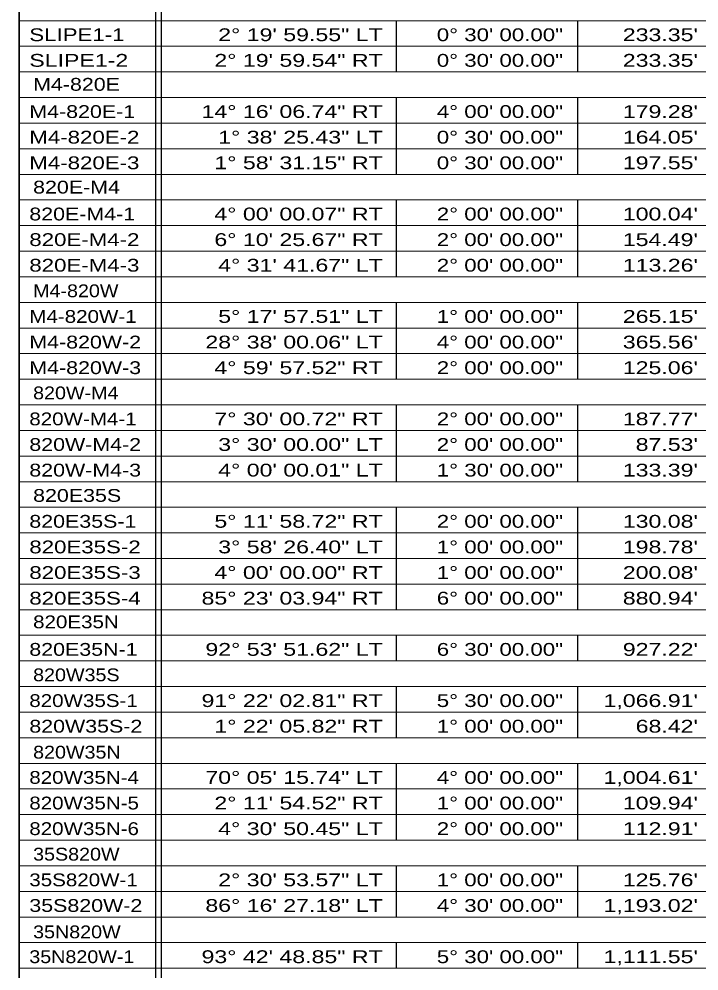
# Model space of a CAD drawing. Extents: x 1953053 to 1967065, y 7363860 to 7371201.
# Drawn here: x 1955933 to 1956571, y 7368493 to 7369385 of the extents above; entities that cross this region are included whole.
import ezdxf
from ezdxf.enums import TextEntityAlignment as Align

# ---------------------------------------------------------------- set-up
doc = ezdxf.new("R2010")
doc.units = 0
doc.header["$LTSCALE"] = 4.8
doc.layers.add('10', color=7, linetype='Continuous')
doc.layers.add('12', color=7, linetype='Continuous', lineweight=25)

msp = doc.modelspace()

# ---------------------------------------------------------------- linework, layer by layer
at = {"layer": '12', "lineweight": 35}
msp.add_line((1955933.385, 7370164.879), (1955933.385, 7367607.746), dxfattribs=at)
at = {"layer": '12'}
for p, q in [((1956061.23, 7370136.079), (1956061.23, 7367607.746)), ((1956066.717, 7370136.079), (1956066.717, 7367607.746)), ((1956286.717, 7369383.746), (1956286.717, 7369335.746)), ((1956456.717, 7369383.746), (1956456.717, 7369335.746)), ((1956286.717, 7369311.746), (1956286.717, 7369239.746)), ((1956456.717, 7369311.746), (1956456.717, 7369239.746)), ((1956286.717, 7369215.746), (1956286.717, 7369143.746)), ((1956456.717, 7369215.746), (1956456.717, 7369143.746)), ((1956286.717, 7369119.746), (1956286.717, 7369047.746)), ((1956456.717, 7369119.746), (1956456.717, 7369047.746)), ((1956286.717, 7369023.746), (1956286.717, 7368951.746)), ((1956456.717, 7369023.746), (1956456.717, 7368951.746)), ((1956286.717, 7368927.746), (1956286.717, 7368831.746)), ((1956456.717, 7368927.746), (1956456.717, 7368831.746)), ((1956286.717, 7368807.746), (1956286.717, 7368783.746)), ((1956456.717, 7368807.746), (1956456.717, 7368783.746)), ((1956286.717, 7368759.746), (1956286.717, 7368711.746)), ((1956456.717, 7368759.746), (1956456.717, 7368711.746)), ((1956286.717, 7368687.746), (1956286.717, 7368615.746)), ((1956456.717, 7368687.746), (1956456.717, 7368615.746)), ((1956286.717, 7368591.746), (1956286.717, 7368543.746)), ((1956456.717, 7368591.746), (1956456.717, 7368543.746)), ((1956286.717, 7368519.746), (1956286.717, 7368495.746)), ((1956456.717, 7368519.746), (1956456.717, 7368495.746))]:
    msp.add_line(p, q, dxfattribs=at)
at = {"layer": '12', "lineweight": 13}
for p, q in [((1955933.385, 7369383.746), (1957656.717, 7369383.746)), ((1955933.385, 7369359.746), (1957656.717, 7369359.746)), ((1955933.385, 7369335.746), (1957656.717, 7369335.746)), ((1955933.385, 7369311.746), (1957656.717, 7369311.746)), ((1955933.385, 7369287.746), (1957656.717, 7369287.746)), ((1955933.385, 7369263.747), (1957656.717, 7369263.747)), ((1955933.385, 7369239.746), (1957656.717, 7369239.746)), ((1955933.385, 7369215.746), (1957656.717, 7369215.746)), ((1955933.385, 7369191.746), (1957656.717, 7369191.746)), ((1955933.385, 7369167.746), (1957656.717, 7369167.746)), ((1955933.385, 7369143.746), (1957656.717, 7369143.746)), ((1955933.385, 7369119.746), (1957656.717, 7369119.746)), ((1955933.385, 7369095.746), (1957656.717, 7369095.746)), ((1955933.385, 7369071.746), (1957656.717, 7369071.746)), ((1955933.385, 7369047.746), (1957656.717, 7369047.746)), ((1955933.385, 7369023.746), (1957656.717, 7369023.746)), ((1955933.385, 7368999.746), (1957656.717, 7368999.746)), ((1955933.385, 7368975.746), (1957656.717, 7368975.746)), ((1955933.385, 7368951.746), (1957656.717, 7368951.746)), ((1955933.385, 7368927.746), (1957656.717, 7368927.746)), ((1955933.385, 7368903.746), (1957656.717, 7368903.746)), ((1955933.385, 7368879.746), (1957656.717, 7368879.746)), ((1955933.385, 7368855.746), (1957656.717, 7368855.746)), ((1955933.385, 7368831.746), (1957656.717, 7368831.746)), ((1955933.385, 7368807.746), (1957656.717, 7368807.746)), ((1955933.385, 7368783.746), (1957656.717, 7368783.746)), ((1955933.385, 7368759.746), (1957656.717, 7368759.746)), ((1955933.385, 7368735.746), (1957656.717, 7368735.746)), ((1955933.385, 7368711.746), (1957656.717, 7368711.746)), ((1955933.385, 7368687.746), (1957656.717, 7368687.746)), ((1955933.385, 7368663.746), (1957656.717, 7368663.746)), ((1955933.385, 7368639.746), (1957656.717, 7368639.746)), ((1955933.385, 7368615.746), (1957656.717, 7368615.746)), ((1955933.385, 7368591.746), (1957656.717, 7368591.746)), ((1955933.385, 7368567.746), (1957656.717, 7368567.746)), ((1955933.385, 7368543.746), (1957656.717, 7368543.746)), ((1955933.385, 7368519.746), (1957656.717, 7368519.746)), ((1955933.385, 7368495.746), (1957656.717, 7368495.746))]:
    msp.add_line(p, q, dxfattribs=at)

# ---------------------------------------------------------------- texts
at = {"layer": '10'}
for s, width, p in [('SLIPE1-1', 1.3, (1955943.006, 7369364.573)), ('SLIPE1-2', 1.35, (1955943.006, 7369340.573)), ('M4-820E', 1.25, (1955946.57, 7369318.084)), ('M4-820E-1', 1.25, (1955943.011, 7369292.569)), ('M4-820E-2', 1.3, (1955943.011, 7369268.569)), ('M4-820E-3', 1.3, (1955943.011, 7369244.569)), ('820E-M4', 1.25, (1955946.57, 7369221.774)), ('820E-M4-1', 1.25, (1955943.011, 7369196.569)), ('820E-M4-2', 1.3, (1955943.011, 7369172.569)), ('820E-M4-3', 1.3, (1955943.011, 7369148.569)), ('M4-820W', 1.15, (1955946.57, 7369124.623)), ('M4-820W-1', 1.2, (1955943.011, 7369100.569)), ('M4-820W-2', 1.25, (1955943.011, 7369076.569)), ('M4-820W-3', 1.25, (1955943.011, 7369052.569)), ('820W-M4', 1.15, (1955946.57, 7369028.925)), ('820W-M4-1', 1.2, (1955943.011, 7369004.569)), ('820W-M4-2', 1.25, (1955943.011, 7368980.569)), ('820W-M4-3', 1.25, (1955943.011, 7368956.569)), ('820E35S', 1.25, (1955946.57, 7368932.849)), ('820E35S-1', 1.25, (1955943.011, 7368908.569)), ('820E35S-2', 1.3, (1955943.011, 7368884.569)), ('820E35S-3', 1.3, (1955943.011, 7368860.569)), ('820E35S-4', 1.3, (1955943.011, 7368836.569)), ('820E35N', 1.2, (1955946.57, 7368814.363)), ('820E35N-1', 1.25, (1955943.011, 7368788.569)), ('820W35S', 1.15, (1955946.57, 7368764.697)), ('820W35S-1', 1.2, (1955943.011, 7368740.569)), ('820W35S-2', 1.25, (1955943.011, 7368716.569)), ('820W35N', 1.15, (1955946.57, 7368692.242)), ('820W35N-4', 1.2, (1955943.011, 7368668.569)), ('820W35N-5', 1.2, (1955943.011, 7368644.569)), ('820W35N-6', 1.2, (1955943.011, 7368620.569)), ('35S820W', 1.15, (1955946.57, 7368596.635)), ('35S820W-1', 1.2, (1955943.011, 7368572.569)), ('35S820W-2', 1.25, (1955943.011, 7368548.569)), ('35N820W', 1.15, (1955946.57, 7368523.834)), ('35N820W-1', 1.15, (1955943.011, 7368500.569))]:
    msp.add_text(s, height=12, dxfattribs=dict(at, width=width)).set_placement(p)
for s, width, p in [('2° 19\' 59.55" LT', 1.35, (1956274.239, 7369364.573)), ('0° 30\' 00.00"', 1.3, (1956443.234, 7369364.573)), ("233.35'", 1.35, (1956569.644, 7369364.573)), ('2° 19\' 59.54" RT', 1.35, (1956274.239, 7369340.573)), ('0° 30\' 00.00"', 1.3, (1956443.234, 7369340.573)), ("233.35'", 1.35, (1956569.644, 7369340.573)), ('14° 16\' 06.74" RT', 1.35, (1956274.244, 7369292.569)), ('4° 00\' 00.00"', 1.3, (1956443.239, 7369292.569)), ("179.28'", 1.35, (1956569.649, 7369292.569)), ('1° 38\' 25.43" LT', 1.35, (1956274.244, 7369268.569)), ('0° 30\' 00.00"', 1.3, (1956443.239, 7369268.569)), ("164.05'", 1.35, (1956569.649, 7369268.569)), ('1° 58\' 31.15" RT', 1.35, (1956274.244, 7369244.569)), ('0° 30\' 00.00"', 1.3, (1956443.239, 7369244.569)), ("197.55'", 1.35, (1956569.649, 7369244.569)), ('4° 00\' 00.07" RT', 1.35, (1956274.244, 7369196.569)), ('2° 00\' 00.00"', 1.3, (1956443.239, 7369196.569)), ("100.04'", 1.35, (1956569.649, 7369196.569)), ('6° 10\' 25.67" RT', 1.35, (1956274.244, 7369172.569)), ('2° 00\' 00.00"', 1.3, (1956443.239, 7369172.569)), ("154.49'", 1.35, (1956569.649, 7369172.569)), ('4° 31\' 41.67" LT', 1.35, (1956274.244, 7369148.569)), ('2° 00\' 00.00"', 1.3, (1956443.239, 7369148.569)), ("113.26'", 1.35, (1956569.649, 7369148.569)), ('5° 17\' 57.51" LT', 1.35, (1956274.244, 7369100.569)), ('1° 00\' 00.00"', 1.3, (1956443.239, 7369100.569)), ("265.15'", 1.35, (1956569.649, 7369100.569)), ('28° 38\' 00.06" LT', 1.35, (1956274.244, 7369076.569)), ('4° 00\' 00.00"', 1.3, (1956443.239, 7369076.569)), ("365.56'", 1.35, (1956569.649, 7369076.569)), ('4° 59\' 57.52" RT', 1.35, (1956274.244, 7369052.569)), ('2° 00\' 00.00"', 1.3, (1956443.239, 7369052.569)), ("125.06'", 1.35, (1956569.649, 7369052.569)), ('7° 30\' 00.72" RT', 1.35, (1956274.244, 7369004.569)), ('2° 00\' 00.00"', 1.3, (1956443.239, 7369004.569)), ("187.77'", 1.35, (1956569.649, 7369004.569)), ('3° 30\' 00.00" LT', 1.35, (1956274.244, 7368980.569)), ('2° 00\' 00.00"', 1.3, (1956443.239, 7368980.569)), ("87.53'", 1.35, (1956569.649, 7368980.569)), ('4° 00\' 00.01" LT', 1.35, (1956274.244, 7368956.569)), ('1° 30\' 00.00"', 1.3, (1956443.239, 7368956.569)), ("133.39'", 1.35, (1956569.649, 7368956.569)), ('5° 11\' 58.72" RT', 1.35, (1956274.244, 7368908.569)), ('2° 00\' 00.00"', 1.3, (1956443.239, 7368908.569)), ("130.08'", 1.35, (1956569.649, 7368908.569)), ('3° 58\' 26.40" LT', 1.35, (1956274.244, 7368884.569)), ('1° 00\' 00.00"', 1.3, (1956443.239, 7368884.569)), ("198.78'", 1.35, (1956569.649, 7368884.569)), ('4° 00\' 00.00" RT', 1.35, (1956274.244, 7368860.569)), ('1° 00\' 00.00"', 1.3, (1956443.239, 7368860.569)), ("200.08'", 1.35, (1956569.649, 7368860.569)), ('85° 23\' 03.94" RT', 1.35, (1956274.244, 7368836.569)), ('6° 00\' 00.00"', 1.3, (1956443.239, 7368836.569)), ("880.94'", 1.35, (1956569.649, 7368836.569)), ('92° 53\' 51.62" LT', 1.35, (1956274.244, 7368788.569)), ('6° 30\' 00.00"', 1.3, (1956443.239, 7368788.569)), ("927.22'", 1.35, (1956569.649, 7368788.569)), ('91° 22\' 02.81" RT', 1.35, (1956274.244, 7368740.569)), ('5° 30\' 00.00"', 1.3, (1956443.239, 7368740.569)), ("1,066.91'", 1.35, (1956569.649, 7368740.569)), ('1° 22\' 05.82" RT', 1.35, (1956274.244, 7368716.569)), ('1° 00\' 00.00"', 1.3, (1956443.239, 7368716.569)), ("68.42'", 1.35, (1956569.649, 7368716.569)), ('70° 05\' 15.74" LT', 1.35, (1956274.244, 7368668.569)), ('4° 00\' 00.00"', 1.3, (1956443.239, 7368668.569)), ("1,004.61'", 1.35, (1956569.649, 7368668.569)), ('2° 11\' 54.52" RT', 1.35, (1956274.244, 7368644.569)), ('1° 00\' 00.00"', 1.3, (1956443.239, 7368644.569)), ("109.94'", 1.35, (1956569.649, 7368644.569)), ('4° 30\' 50.45" LT', 1.35, (1956274.244, 7368620.569)), ('2° 00\' 00.00"', 1.3, (1956443.239, 7368620.569)), ("112.91'", 1.35, (1956569.649, 7368620.569)), ('2° 30\' 53.57" LT', 1.35, (1956274.244, 7368572.569)), ('1° 00\' 00.00"', 1.3, (1956443.239, 7368572.569)), ("125.76'", 1.35, (1956569.649, 7368572.569)), ('86° 16\' 27.18" LT', 1.35, (1956274.244, 7368548.569)), ('4° 30\' 00.00"', 1.3, (1956443.239, 7368548.569)), ("1,193.02'", 1.35, (1956569.649, 7368548.569)), ('93° 42\' 48.85" RT', 1.35, (1956274.244, 7368500.569)), ('5° 30\' 00.00"', 1.3, (1956443.239, 7368500.569)), ("1,111.55'", 1.35, (1956569.649, 7368500.569))]:
    msp.add_text(s, height=12, dxfattribs=dict(at, width=width)).set_placement(p, align=Align.RIGHT)

doc.saveas('drawing.dxf')
